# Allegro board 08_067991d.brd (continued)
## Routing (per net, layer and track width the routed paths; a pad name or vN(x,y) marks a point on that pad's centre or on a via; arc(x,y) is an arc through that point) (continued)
DGND: length 977.2
  TOP w0.203: v1(46.95,55.13) 47.15,55.33 47.15,55.51 47.2,55.56 U11.1 47.2,56.46 47.5,56.76 ; U11.38 v1(47,50.32) ; v1(41.9,51.82) U11.20 40.38,51.82 40.26,51.94 ; U11.30 v1(44.2,50.02) ; U10.9 80.51,25.65 v1(80.77,25.91) ; U11.32 v1(45.2,50.02) ; U11.44 v1(47,53.32) ; v1(42.2,50.02) U11.26 42.2,48.33 ; U11.4 v1(45.7,55.12) ; U11.10 v1(42.7,55.18)
  TOP w0.254: U12.20 50.55,82.53 C86.2 ; v1(42.04,82.3) 41.77,82.03 U12.42 ; v1(45.47,76.2) 45.24,76.42 U12.7 ; U7.C2 v1(20.83,74.41) ; U12.25 v1(48.48,85.96) ; U12.33 43.74,85.14 v1(43.31,84.71) ; U16.11 53.07,115.24 52.57,114.74 ; U12.38 39.39,84.03 C89.2 39.19,84.3 39.42,84.53 U12.37 v1(42.11,84.53) ; 46.14,44.23 46.14,46.05 45.2,46.99 U11.32 ; 43.12,44.31 43.12,46.01 44.2,47.08 U11.30 ; 52.57,114.74 v1(52.32,114.49) 52.07,114.74 U16.21 ; 52.57,114.74 U16.15 ; U9.C2 v1(20.83,97.27) ; U12.12 v1(48.34,77.6) ; U12.30 45.24,84.81 v1(45.47,84.58)
  TOP w0.305: 41.66,77.6 U12.1
  TOP w0.508: C104.1 v1(9.32,45.34) ; 43.07,112.98 R60.1 ; R60.1 43.07,114.22 ; R60.1 v1(42.29,113.6) ; 26.25,53.19 P15.8 28.61,53.19 ; 59.11,43.96 C40.1 ; C40.1 60.27,43.96 ; C40.1 v1(59.69,42.97) ; 61.26,12.7 P13.1 ; P13.1 62.69,11.26 ; P13.1 62.69,14.14 ; P13.1 64.13,12.7 ; C117.1 83.77,22.86 ; C117.1 82.87,21.81 ; C117.1 82.87,23.91 ; 40.94,28.11 C39.2 ; C39.2 v1(41.53,27.43) ; C39.2 42.11,28.11 ; P7.1 2.4,95.23 ; P7.1 2.4,91.92 ; P7.1 3.76,93.57 ; 44.65,68.73 P2.10 ; P2.10 44.65,71.09 ; P2.10 45.83,69.91 ; P2.10 43.47,69.91 ; DS12.C 51.54,2 ; DS12.C 50.9,2.65 ; DS12.C 50.25,2 ; 50.8,123.27 C73.1 ; C73.1 52.08,124.07 ; C73.1 50.8,124.87 ; C73.1 49.52,124.07 ; P15.10 28.61,50.65 ; P15.10 26.25,50.65 ; P15.10 27.43,49.47 ; 41.5,95.75 P5.4 ; P5.4 42.68,96.93 ; P5.4 42.68,94.57 ; P5.4 43.86,95.75 ; C26.2 v1(54.74,31.98) ; v1(76.2,118.49) C77.2 ; C77.2 74.99,119.55 ; C77.2 74.99,117.44 ; 8.16,81.42 C54.2 7.57,81.97 ; 50.22,78.03 C94.2 ; C94.2 51.38,78.03 ; C94.2 v1(50.8,77.27) ; 21.44,95.04 C58.2 ; C58.2 v1(21.44,96.35) ; C58.2 21.98,95.62 ; 23.86,44.83 DS2.C ; DS2.C 24.6,45.47 ; DS2.C 24.6,44.2 ; 55.36,74.42 C93.N ; C93.N 56.86,73.37 ; C93.N 58.36,74.42 ; C93.N 56.86,75.48 ; P2.6 40.75,69.91 ; P2.6 39.57,68.73 ; P2.6 39.57,71.09 ; P2.6 38.39,69.91 ; P1.1 26.78,19.22 ; P1.1 28.21,17.78 ; P1.1 25.34,17.78 ; P1.1 26.78,16.34 ; C90.2 v1(41.03,88.42) ; C90.2 40.48,87.63 ; C90.2 41.03,87.05 ; U15.7 v1(78.36,60.7) ; 52.93,25.43 C28.1 ; C28.1 53.47,24.85 ; C28.1 v1(53.47,26.67) ; P5.6 46.4,95.75 ; P5.6 45.22,96.93 ; P5.6 44.04,95.75 ; P5.6 45.22,94.57 ; C43.2 21.98,76.06 ; C43.2 v1(21.44,75.33) ; C43.2 21.44,76.65 ; 47.76,94.57 P5.8 ; P5.8 47.76,96.93 ; P5.8 46.58,95.75 ; P5.8 48.94,95.75 ; DS8.C 45.12,2 ; DS8.C 44.27,2.65 ; DS8.C 43.62,2 ; 66.9,50.45 S2.2A ; S2.2A 65.05,51.2 ; S2.2A v1(69.09,51.2) ; S2.2A 66.9,51.95 ; 28.61,55.73 P15.6 26.25,55.73 ; 71.5,61.41 U15.1 ; U15.1 72.85,61.97 ; U15.1 v1(69.85,61.97) ; U15.1 71.5,62.53 ; 55.36,87.63 C83.N ; C83.N 58.36,87.63 ; C83.N 56.86,86.58 ; C83.N 56.86,88.68 ; R62.1 60.94,115.43 ; R62.1 v1(61.85,114.81) ; R62.1 60.94,114.19 ; C75.2 v1(29.72,109.34) ; C75.2 30.92,108.28 ; C75.2 30.92,110.39 ; 37.46,72.22 P9.2 ; P9.2 38.65,73.41 ; P9.2 37.46,74.59 ; P9.2 36.28,73.41 ; 29.97,76.16 TP7.1 ; TP7.1 28.79,77.34 ; TP7.1 29.97,78.52 ; TP7.1 31.15,77.34 ; C29.2 60.99,25.43 ; C29.2 v1(60.44,26.67) ; C29.2 60.44,24.85 ; P2.14 50.91,69.91 ; P2.14 48.55,69.91 ; P2.14 49.73,71.09 ; P2.14 49.73,68.73 ; 33.56,86.58 C84.N ; C84.N 33.56,88.68 ; C84.N 35.06,87.63 ; C84.N 32.06,87.63 ; 8.16,104.28 C64.2 7.57,104.83 ; TP5.1 22.77,44.83 ; TP5.1 20.41,44.83 ; TP5.1 21.59,43.65 ; TP5.1 21.59,46.01 ; 69.59,44.83 TP6.1 ; TP6.1 71.95,44.83 ; TP6.1 70.77,46.01 ; TP6.1 70.77,43.65 ; C96.2 51.38,85.72 ; C96.2 50.22,85.72 ; C96.2 50.8,86.26 ; U14.7 v1(69.09,60.8) ; 41.67,75.56 R69.1 ; R69.1 42.24,74.94 ; R69.1 42.24,76.19 ; C110.2 v1(9.02,62.36) ; 46.01,69.91 P2.12 ; P2.12 48.37,69.91 ; P2.12 47.19,68.73 ; P2.12 47.19,71.09 ; P6.1 2.4,72.37 ; P6.1 3.76,70.71 ; P6.1 2.4,69.06 ; C11.2 v1(46.61,43.63) ; 47.63,73.91 C80.1 46.9,74.66 ; 49.12,95.75 P5.10 ; P5.10 50.3,96.93 ; P5.10 50.3,94.57 ; P5.10 51.48,95.75 ; C103.2 v1(7.29,52.58) ; C103.2 8.22,51.83 ; C103.2 8.22,53.33 ; 35.93,24.85 C20.1 ; C20.1 36.48,25.43 ; C20.1 v1(35.93,26.67) ; 61.01,58.26 U14.4 ; U14.4 63.7,58.26 ; U14.4 v1(62.36,57.52) ; 42.11,68.73 P2.8 ; P2.8 43.29,69.91 ; P2.8 42.11,71.09 ; P2.8 40.93,69.91 ; 51.09,69.91 P2.16 ; P2.16 52.27,71.09 ; P2.16 53.45,69.91 ; P2.16 52.27,68.73 ; P15.2 28.61,60.81 ; P15.2 27.43,61.99 ; P15.2 26.25,60.81 ; C56.1 v1(17.14,75.05) ; R80.2 v1(18.01,45.47) ; R80.2 17.26,46.09 ; R80.2 17.26,44.84 ; 55.62,52.88 C9.2 ; C9.2 56.16,53.47 ; C9.2 55.62,54.05 ; R18.2 R19.2 54.99,51.82 ; R18.2 54.99,50.67 ; R18.2 54.16,49.85 v1(54.23,49.78) ; C37.1 v1(57.53,48.42) ; C86.2 v1(51.44,82.78) ; 9.97,41.11 C101.2 9.07,42.16 ; 65.89,6.98 P13.GND ; P13.GND 67.13,5.73 ; P13.GND 68.38,6.98 ; P13.GND 67.13,8.23 ; P15.12 28.61,48.11 ; P15.12 26.25,48.11 ; P15.12 27.43,49.29 ; P15.12 27.43,46.93 ; 51.66,95.75 P5.12 ; P5.12 52.84,94.57 ; P5.12 52.84,96.93 ; P5.12 54.02,95.75 ; v1(82.03,28.2) C116.2 82.68,28.96 ; R58.2 v1(6.44,87.3) ; C100.1 v1(74.83,63.49) ; C79.2 53.96,122.21 ; C79.2 53.21,122.94 ; C79.2 52.46,122.21 ; P10.10 75.18,90.27 ; P10.10 74.07,89.15 ; P10.10 75.18,88.04 ; P10.10 76.3,89.15 ; C57.2 v1(21.44,98.19) ; C57.2 21.44,99.51 ; C57.2 21.98,98.92 ; U15.2 71.5,61.26 ; U15.2 71.5,60.14 ; U15.2 72.85,60.7 ; U15.2 v1(69.85,60.7) ; JP2.3 52.49,103.88 ; JP2.3 50.13,103.88 ; JP2.3 51.31,105.06 ; JP2.3 51.31,102.69 ; R106.2 v1(83.32,50.28) ; 8.57,112.4 C48.2 ; C48.2 v1(9.16,111.63) ; C48.2 9.74,112.4 ; R116.1 v1(76.71,22.35) ; P5.2 40.14,96.93 ; P5.2 40.14,94.57 ; P5.2 41.32,95.75 ; P5.2 38.96,95.75 ; R28.2 v1(58.29,58.41) ; 9.32,126.19 C47.2 ; C47.2 10.49,126.19 ; C47.2 v1(9.91,126.96) ; 77.91,48.13 D2.A ; D2.A 79.34,48.13 ; D2.A v1(78.63,47.07) ; D2.A 78.63,49 ; 9.28,55.68 C106.2 ; C106.2 8.73,56.26 ; C106.2 9.28,56.85 ; U15.4 v1(69.85,58.16) ; U15.4 71.5,58.72 ; U15.4 72.85,58.16 ; U15.4 71.5,57.6 ; v1(42.73,43.63) C13.2 43.12,44.31 ; C36.1 42.11,39.66 ; C36.1 40.94,39.66 ; C36.1 v1(41.53,38.7) ; 4.95,37.02 DS10.C ; DS10.C 5.97,37.78 ; DS10.C 5.97,36.26 ; DS10.C 6.99,37.02 ; C76.1 30.92,119.55 ; C76.1 30.92,117.44 ; C76.1 v1(29.72,118.49) ; 6.57,82 R49.2 5.95,81.42 ; 57.91,51.2 S2.1A ; S2.1A 61.95,51.2 ; S2.1A 60.1,51.95 ; S2.1A 60.1,50.45 ; R50.2 v1(6.44,64.44) ; C53.2 84.19,36.66 ; C53.2 v1(83.44,35.81) ; C53.2 82.69,36.66 ; C92.2 v1(44.44,88.42) ; 18.07,56.87 DS1.C ; DS1.C 19.77,56.87 ; DS1.C v1(18.92,55.75) ; DS1.C 18.92,57.72 ; P2.18 54.81,71.09 ; P2.18 54.81,68.73 ; P2.18 55.99,69.91 ; P2.18 53.63,69.91 ; 62.62,93.1 R77.2 ; R77.2 62.62,94.35 ; R77.2 62.05,93.73 ; P2.4 37.03,71.09 ; P2.4 37.03,68.73 ; P2.4 38.21,69.91 ; P2.4 35.85,69.91 ; C44.2 21.44,73.35 ; C44.2 21.44,72.18 ; C44.2 21.98,72.76 ; 71.5,58.87 U15.3 ; U15.3 72.85,59.43 ; U15.3 71.5,59.99 ; U15.3 v1(69.85,59.43) ; R112.1 v1(78.11,30.48) ; 28.61,58.27 P15.4 26.25,58.27 ; C16.2 68.74,64.58 ; C16.2 v1(69.72,64) ; C16.2 68.74,63.41 ; C19.2 v1(30.23,31.98) ; C38.1 v1(31.5,48.42) ; C38.1 30.91,47.43 ; C38.1 32.08,47.43 ; C21.2 v1(28.96,26.67) ; C21.2 28.96,24.85 ; C21.2 28.42,25.43 ; C91.2 v1(37.97,85.05) ; C65.2 v1(7.46,87.3) ; C69.2 v1(45.85,120.87) ; TP8.1 81.19,78.23 ; TP8.1 80.01,79.41 ; TP8.1 80.01,77.05 ; TP8.1 78.83,78.23 ; 6.57,104.86 R57.2 5.95,104.28 ; 45.52,25.42 C41.1 ; C41.1 46.69,25.42 ; C41.1 v1(46.1,24.74) ; C42.1 80.35,46.85 ; C42.1 v1(79.43,46.1) ; C42.1 80.35,45.35 ; 34.49,68.73 P2.2 ; P2.2 33.31,69.91 ; P2.2 35.67,69.91 ; P2.2 34.49,71.09 ; C72.2 v1(62.23,112.9) ; C72.2 61.42,112.15 ; C72.2 61.42,113.65 ; 2.4,115.29 P4.1 ; P4.1 v1(4.06,116.94) ; P4.1 2.4,118.59 ; C82.2 v1(87,46.99) ; R23.2 v1(64.13,64.89) ; C18.2 v1(34.66,31.98) ; 84.59,37.6 R107.1 ; R107.1 85.84,37.6 ; R107.1 v1(85.22,36.96) ; R114.1 v1(78.11,29.08) ; C27.2 v1(59.17,31.98) ; R82.2 v1(8.38,51.18) ; C55.2 v1(7.46,64.44) ; C89.2 v1(39.12,85.05) ; R25.2 v1(58.29,61.97) ; C78.1 74.99,110.39 ; C78.1 74.99,108.28 ; C78.1 v1(76.2,109.34) ; R109.1 v1(87,44.7) ; C99.2 v1(39.12,80.53) ; C102.2 v1(16.84,44.07) ; C63.1 v1(17.14,97.91) ; C98.2 v1(37.97,80.53) ; R85.1 v1(11.18,48.51)
  L2_GND w0.508: 34.49,68.73 P2.2 ; P2.2 33.31,69.91 ; P2.2 34.49,71.09 ; P2.2 35.67,69.91 ; P15.12 27.43,49.29 ; P15.12 28.61,48.11 ; P15.12 26.25,48.11 ; P15.12 27.43,46.93 ; 21.59,43.65 TP5.1 ; TP5.1 21.59,46.01 ; TP5.1 22.77,44.83 ; TP5.1 20.41,44.83 ; 26.25,53.19 P15.8 ; P15.8 27.43,54.37 ; P15.8 27.43,52.01 ; P15.8 28.61,53.19 ; 54.81,68.73 P2.18 ; P2.18 53.63,69.91 ; P2.18 54.81,71.09 ; P2.18 55.99,69.91 ; P1.1 28.21,17.78 ; P1.1 26.78,16.34 ; P1.1 25.34,17.78 ; P1.1 26.78,19.22 ; 75.18,88.04 P10.10 ; P10.10 76.3,89.15 ; P10.10 74.07,89.15 ; P10.10 75.18,90.27 ; 38.96,95.75 P5.2 ; P5.2 41.32,95.75 ; P5.2 40.14,96.93 ; P5.2 40.14,94.57 ; 26.25,50.65 P15.10 ; P15.10 28.61,50.65 ; P15.10 27.43,51.83 ; P15.10 27.43,49.47 ; P2.14 49.73,71.09 ; P2.14 48.55,69.91 ; P2.14 50.91,69.91 ; P2.14 49.73,68.73 ; P9.2 37.46,74.59 ; P9.2 38.65,73.41 ; P9.2 36.28,73.41 ; P9.2 37.46,72.22 ; 44.04,95.75 P5.6 ; P5.6 45.22,96.93 ; P5.6 45.22,94.57 ; P5.6 46.4,95.75 ; P2.12 48.37,69.91 ; P2.12 46.01,69.91 ; P2.12 47.19,68.73 ; P2.12 47.19,71.09 ; P13.GND 67.13,8.23 ; P13.GND 65.89,6.98 ; P13.GND 68.38,6.98 ; P13.GND 67.13,5.73 ; TP6.1 71.95,44.83 ; TP6.1 69.59,44.83 ; TP6.1 70.77,46.01 ; TP6.1 70.77,43.65 ; TP8.1 81.19,78.23 ; TP8.1 78.83,78.23 ; TP8.1 80.01,79.41 ; TP8.1 80.01,77.05 ; P15.4 27.43,59.45 ; P15.4 27.43,57.09 ; P15.4 28.61,58.27 ; P15.4 26.25,58.27 ; P2.10 45.83,69.91 ; P2.10 44.65,68.73 ; P2.10 44.65,71.09 ; P2.10 43.47,69.91 ; 61.26,12.7 P13.1 ; P13.1 64.13,12.7 ; P13.1 62.69,14.14 ; P13.1 62.69,11.26 ; 51.09,69.91 P2.16 ; P2.16 52.27,71.09 ; P2.16 52.27,68.73 ; P2.16 53.45,69.91 ; P2.8 43.29,69.91 ; P2.8 42.11,68.73 ; P2.8 40.93,69.91 ; P2.8 42.11,71.09 ; P2.6 40.75,69.91 ; P2.6 39.57,68.73 ; P2.6 38.39,69.91 ; P2.6 39.57,71.09 ; P15.6 28.61,55.73 ; P15.6 27.43,56.91 ; P15.6 26.25,55.73 ; P15.6 27.43,54.55 ; 41.5,95.75 P5.4 ; P5.4 42.68,96.93 ; P5.4 42.68,94.57 ; P5.4 43.86,95.75 ; 46.58,95.75 P5.8 ; P5.8 47.76,96.93 ; P5.8 48.94,95.75 ; P5.8 47.76,94.57 ; TP7.1 29.97,78.52 ; TP7.1 31.15,77.34 ; TP7.1 29.97,76.16 ; TP7.1 28.79,77.34 ; 26.25,60.81 P15.2 ; P15.2 27.43,59.63 ; P15.2 28.61,60.81 ; P15.2 27.43,61.99 ; 49.12,95.75 P5.10 ; P5.10 50.3,94.57 ; P5.10 51.48,95.75 ; P5.10 50.3,96.93 ; JP2.3 52.49,103.88 ; JP2.3 51.31,105.06 ; JP2.3 51.31,102.69 ; JP2.3 50.13,103.88 ; 35.85,69.91 P2.4 ; P2.4 37.03,71.09 ; P2.4 37.03,68.73 ; P2.4 38.21,69.91 ; P5.12 52.84,96.93 ; P5.12 52.84,94.57 ; P5.12 51.66,95.75 ; P5.12 54.02,95.75
  L3_PWR w0.508: 69.59,44.83 TP6.1 ; TP6.1 71.95,44.83 ; TP6.1 70.77,46.01 ; TP6.1 70.77,43.65 ; P13.GND 68.38,6.98 ; P13.GND 67.13,5.73 ; P13.GND 65.89,6.98 ; P13.GND 67.13,8.23 ; P5.4 43.86,95.75 ; P5.4 42.68,94.57 ; P5.4 41.5,95.75 ; P5.4 42.68,96.93 ; P15.12 28.61,48.11 ; P15.12 27.43,49.29 ; P15.12 26.25,48.11 ; P15.12 27.43,46.93 ; 54.81,68.73 P2.18 ; P2.18 54.81,71.09 ; P2.18 55.99,69.91 ; P2.18 53.63,69.91 ; P15.10 28.61,50.65 ; P15.10 27.43,51.83 ; P15.10 26.25,50.65 ; P15.10 27.43,49.47 ; 62.69,11.26 P13.1 ; P13.1 64.13,12.7 ; P13.1 62.69,14.14 ; P13.1 61.26,12.7 ; P2.4 38.21,69.91 ; P2.4 37.03,71.09 ; P2.4 37.03,68.73 ; P5.12 54.02,95.75 ; P5.12 52.84,94.57 ; P5.12 52.84,96.93 ; P1.1 28.21,17.78 ; P1.1 26.78,16.34 ; P1.1 26.78,19.22 ; P1.1 25.34,17.78 ; TP7.1 31.15,77.34 ; TP7.1 29.97,78.52 ; TP7.1 28.79,77.34 ; TP7.1 29.97,76.16 ; 49.73,68.73 P2.14 49.73,71.09 ; P5.10 50.3,96.93 ; P5.10 50.3,94.57 ; P5.10 51.48,95.75 ; P15.6 28.61,55.73 ; P15.6 26.25,55.73 ; P15.6 27.43,56.91 ; P15.6 27.43,54.55 ; P15.8 28.61,53.19 ; P15.8 26.25,53.19 ; P15.8 27.43,54.37 ; P15.8 27.43,52.01 ; 42.11,68.73 P2.8 ; P2.8 40.93,69.91 ; P2.8 42.11,71.09 ; 26.25,60.81 P15.2 ; P15.2 27.43,61.99 ; P15.2 27.43,59.63 ; P15.2 28.61,60.81 ; 47.76,96.93 P5.8 47.76,94.57 ; 45.22,94.57 P5.6 ; P5.6 45.22,96.93 ; P5.6 44.04,95.75 ; 75.18,88.04 P10.10 ; P10.10 75.18,90.27 ; P10.10 76.3,89.15 ; P10.10 74.07,89.15 ; 80.01,77.05 TP8.1 ; TP8.1 81.19,78.23 ; TP8.1 80.01,79.41 ; TP8.1 78.83,78.23 ; P15.4 28.61,58.27 ; P15.4 27.43,57.09 ; P15.4 26.25,58.27 ; P15.4 27.43,59.45 ; 34.49,68.73 P2.2 ; P2.2 33.31,69.91 ; P2.2 34.49,71.09 ; 20.41,44.83 TP5.1 ; TP5.1 21.59,46.01 ; TP5.1 22.77,44.83 ; TP5.1 21.59,43.65 ; JP2.3 52.49,103.88 ; JP2.3 51.31,102.69 ; JP2.3 51.31,105.06 ; JP2.3 50.13,103.88 ; P9.2 37.46,74.59 ; P9.2 36.28,73.41 ; P9.2 37.46,72.22 ; P9.2 38.65,73.41 ; P5.2 40.14,96.93 ; P5.2 38.96,95.75 ; P5.2 41.32,95.75 ; P5.2 40.14,94.57 ; P2.16 52.27,71.09 ; P2.16 53.45,69.91 ; P2.16 52.27,68.73
  L5_GND w0.508: P15.10 28.61,50.65 ; P15.10 27.43,49.47 ; P15.10 26.25,50.65 ; P15.10 27.43,51.83 ; P2.18 54.81,71.09 ; P2.18 55.99,69.91 ; P2.18 54.81,68.73 ; P2.18 53.63,69.91 ; P2.10 44.65,71.09 ; P2.10 45.83,69.91 ; P2.10 44.65,68.73 ; P2.10 43.47,69.91 ; 51.31,102.69 JP2.3 ; JP2.3 51.31,105.06 ; JP2.3 50.13,103.88 ; JP2.3 52.49,103.88 ; P5.10 51.48,95.75 ; P5.10 50.3,94.57 ; P5.10 49.12,95.75 ; P5.10 50.3,96.93 ; 29.97,76.16 TP7.1 ; TP7.1 31.15,77.34 ; TP7.1 28.79,77.34 ; TP7.1 29.97,78.52 ; 69.59,44.83 TP6.1 ; TP6.1 70.77,46.01 ; TP6.1 70.77,43.65 ; TP6.1 71.95,44.83 ; P2.2 35.67,69.91 ; P2.2 33.31,69.91 ; P2.2 34.49,71.09 ; P2.2 34.49,68.73 ; 52.27,68.73 P2.16 ; P2.16 51.09,69.91 ; P2.16 52.27,71.09 ; P2.16 53.45,69.91 ; P5.2 41.32,95.75 ; P5.2 40.14,94.57 ; P5.2 38.96,95.75 ; P5.2 40.14,96.93 ; 26.25,60.81 P15.2 ; P15.2 27.43,59.63 ; P15.2 27.43,61.99 ; P15.2 28.61,60.81 ; 47.19,68.73 P2.12 ; P2.12 48.37,69.91 ; P2.12 46.01,69.91 ; P2.12 47.19,71.09 ; P1.1 26.78,19.22 ; P1.1 28.21,17.78 ; P1.1 26.78,16.34 ; P1.1 25.34,17.78 ; P13.GND 67.13,8.23 ; P13.GND 67.13,5.73 ; P13.GND 68.38,6.98 ; P13.GND 65.89,6.98 ; P2.6 39.57,71.09 ; P2.6 39.57,68.73 ; P2.6 40.75,69.91 ; P2.6 38.39,69.91 ; 51.66,95.75 P5.12 ; P5.12 52.84,94.57 ; P5.12 54.02,95.75 ; P5.12 52.84,96.93 ; P15.12 28.61,48.11 ; P15.12 26.25,48.11 ; P15.12 27.43,49.29 ; P15.12 27.43,46.93 ; 46.58,95.75 P5.8 ; P5.8 47.76,94.57 ; P5.8 47.76,96.93 ; P5.8 48.94,95.75 ; 40.93,69.91 P2.8 ; P2.8 42.11,71.09 ; P2.8 43.29,69.91 ; P2.8 42.11,68.73 ; 78.83,78.23 TP8.1 ; TP8.1 80.01,79.41 ; TP8.1 80.01,77.05 ; TP8.1 81.19,78.23 ; 45.22,94.57 P5.6 ; P5.6 44.04,95.75 ; P5.6 45.22,96.93 ; P5.6 46.4,95.75 ; 62.69,11.26 P13.1 ; P13.1 64.13,12.7 ; P13.1 62.69,14.14 ; P13.1 61.26,12.7 ; 21.59,43.65 TP5.1 ; TP5.1 20.41,44.83 ; TP5.1 22.77,44.83 ; TP5.1 21.59,46.01 ; P10.10 76.3,89.15 ; P10.10 75.18,90.27 ; P10.10 74.07,89.15 ; P10.10 75.18,88.04 ; 26.25,53.19 P15.8 ; P15.8 27.43,52.01 ; P15.8 27.43,54.37 ; P15.8 28.61,53.19 ; P9.2 38.65,73.41 ; P9.2 37.46,72.22 ; P9.2 36.28,73.41 ; P9.2 37.46,74.59 ; 41.5,95.75 P5.4 ; P5.4 42.68,96.93 ; P5.4 42.68,94.57 ; P5.4 43.86,95.75 ; P15.6 27.43,56.91 ; P15.6 28.61,55.73 ; P15.6 27.43,54.55 ; P15.6 26.25,55.73 ; 49.73,68.73 P2.14 ; P2.14 49.73,71.09 ; P2.14 50.91,69.91 ; P2.14 48.55,69.91 ; 27.43,57.09 P15.4 ; P15.4 27.43,59.45 ; P15.4 26.25,58.27 ; P15.4 28.61,58.27 ; 37.03,68.73 P2.4 ; P2.4 35.85,69.91 ; P2.4 38.21,69.91 ; P2.4 37.03,71.09
  BOTTOM w0.508: P5.12 52.84,96.93 ; P5.12 54.02,95.75 ; P5.12 51.66,95.75 ; P5.12 52.84,94.57 ; 23.25,19.38 C123.1 ; C123.1 24.75,19.38 ; C123.1 24,20.1 ; TP5.1 22.77,44.83 ; TP5.1 21.59,43.65 ; TP5.1 21.59,46.01 ; TP5.1 20.41,44.83 ; 35.85,69.91 P2.4 ; P2.4 37.03,68.73 ; P2.4 37.03,71.09 ; P2.4 38.21,69.91 ; D6.3 33,33.42 ; D6.3 32.44,32.65 ; D6.3 31.89,33.42 ; D6.3 32.44,34.2 ; 26.78,16.34 P1.1 ; P1.1 25.34,17.78 ; P1.1 28.21,17.78 ; P5.6 46.4,95.75 ; P5.6 45.22,96.93 ; P5.6 45.22,94.57 ; P5.6 44.04,95.75 ; C3.2 41.65,52.07 v1(41.9,51.82) ; C3.2 41.14,52.65 ; C3.2 41.14,51.49 ; C5.2 43.51,55.62 ; C5.2 42.93,55.08 ; C5.2 42.34,55.62 ; 28.61,53.19 P15.8 26.25,53.19 ; 51.09,69.91 P2.16 ; P2.16 52.27,68.73 ; P2.16 53.45,69.91 ; P2.16 52.27,71.09 ; 44.45,55.09 C1.2 43.87,55.63 ; 26.25,60.81 P15.2 ; P15.2 27.43,59.63 ; P15.2 27.43,61.99 ; P15.2 28.61,60.81 ; 42.6,50.15 C15.2 ; C15.2 43.77,50.15 ; C15.2 43.18,50.69 ; JP2.3 51.31,105.06 ; JP2.3 51.31,102.69 ; JP2.3 52.49,103.88 ; JP2.3 50.13,103.88 ; P2.14 49.73,71.09 ; P2.14 49.73,68.73 ; P2.14 50.91,69.91 ; P2.14 48.55,69.91 ; 56.4,33.42 D4.3 ; D4.3 56.96,34.2 ; D4.3 56.96,32.65 ; D4.3 57.51,33.42 ; v1(39.12,80.53) 39.73,80.53 C87.2 C85.2 ; P2.10 44.65,71.09 ; P2.10 43.47,69.91 ; P2.10 45.83,69.91 ; P2.10 44.65,68.73 ; P9.2 37.46,74.59 ; P9.2 37.46,72.22 ; P9.2 36.28,73.41 ; P9.2 38.65,73.41 ; P5.4 42.68,96.93 ; P5.4 43.86,95.75 ; P5.4 41.5,95.75 ; P5.4 42.68,94.57 ; 52.71,53.34 C8.1 51.98,54.09 ; P13.1 64.13,12.7 ; P13.1 62.69,14.14 ; P13.1 62.69,11.26 ; P13.1 61.26,12.7 ; 67.13,5.73 P13.GND ; P13.GND 68.38,6.98 ; P13.GND 65.89,6.98 ; P13.GND 67.13,8.23 ; P2.6 40.75,69.91 ; P2.6 38.39,69.91 ; P2.6 39.57,68.73 ; P2.6 39.57,71.09 ; P5.8 47.76,96.93 ; P5.8 48.94,95.75 ; P5.8 47.76,94.57 ; P5.8 46.58,95.75 ; 28.79,77.34 TP7.1 ; TP7.1 29.97,78.52 ; TP7.1 29.97,76.16 ; TP7.1 31.15,77.34 ; C4.2 47,55.19 ; C4.2 47,54.23 v1(47,53.32) ; C4.2 46.45,54.61 ; 46.01,69.91 P2.12 ; P2.12 48.37,69.91 ; P2.12 47.19,68.73 ; P2.12 47.19,71.09 ; P5.10 50.3,96.93 ; P5.10 50.3,94.57 ; P5.10 51.48,95.75 ; P5.10 49.12,95.75 ; 34.49,68.73 P2.2 ; P2.2 34.49,71.09 ; P2.2 35.67,69.91 ; P2.2 33.31,69.91 ; P2.18 54.81,71.09 ; P2.18 55.99,69.91 ; P2.18 53.63,69.91 ; P2.18 54.81,68.73 ; v1(45.2,50.02) 45.2,49.27 C10.1 ; P2.8 43.29,69.91 ; P2.8 42.11,71.09 ; P2.8 42.11,68.73 ; P2.8 40.93,69.91 ; 53.77,109.74 C118.2 54.36,109.19 ; P10.10 76.3,89.15 ; P10.10 74.07,89.15 ; P10.10 75.18,90.27 ; P10.10 75.18,88.04 ; v1(45.7,55.12) 45.47,55.35 C2.2 ; P15.6 27.43,56.91 ; P15.6 26.25,55.73 ; P15.6 28.61,55.73 ; 51.17,55.19 C7.2 51.72,54.61 ; 70.77,43.65 TP6.1 ; TP6.1 71.95,44.83 ; TP6.1 69.59,44.83 ; TP6.1 70.77,46.01 ; v1(44.2,50.02) 44.2,50.02 C14.2 ; C88.2 v1(41.52,76.97) ; C88.2 42.07,77.72 ; C88.2 41.52,78.31 ; P15.4 28.61,58.27 ; P15.4 26.25,58.27 ; P15.4 27.43,59.45 ; TP8.1 80.01,79.41 ; TP8.1 80.01,77.05 ; TP8.1 78.83,78.23 ; TP8.1 81.19,78.23 ; 40.14,94.57 P5.2 ; P5.2 40.14,96.93 ; P5.2 41.32,95.75 ; P5.2 38.96,95.75 ; P15.12 28.61,48.11 ; P15.12 26.25,48.11 ; P15.12 27.43,46.93 ; C12.1 46.82,50.15 ; C12.1 46.23,50.69 ; C12.1 45.65,50.15 ; C81.2 37.21,51.17 v1(37.21,50.29) ; 46.45,53.59 C6.2 47,53.01 ; 28.61,50.65 P15.10 26.25,50.65
  vias: v1(2.67,114.36) v1(2.67,112.46) v1(2.67,109.92) v1(2.67,107.38) v1(2.67,100.39) v1(2.67,94.68) v1(2.67,90.87) v1(2.67,87.69) v1(2.67,85.15) v1(2.67,82.61) v1(2.67,78.8) v1(2.67,76.26) v1(2.67,68.64) v1(3.81,33.78) v1(3.81,31.24) v1(3.81,28.7) v1(3.81,26.16) v1(3.81,23.62) v1(3.81,16) v1(3.81,13.46) v1(3.81,10.92) v1(5.08,66.67) v1(5.08,64.14) v1(5.08,61.59) v1(5.08,59.05) v1(5.08,56.52) v1(5.08,53.98) v1(5.08,51.43) v1(5.08,48.89) v1(5.08,46.35) v1(5.08,43.81) v1(5.08,41.27) v1(5.08,38.73) v1(5.08,36.2) v1(5.21,114.36) v1(5.21,112.46) v1(5.21,109.92) v1(5.21,107.38) v1(5.21,94.68) v1(5.21,90.87) v1(5.21,87.69) v1(5.21,85.15) v1(5.21,82.61) v1(5.21,71.18) v1(5.21,68.64) v1(6.22,78.74) v1(6.22,76.2) v1(6.22,61.34) v1(6.22,60.71) v1(6.22,60.07) v1(6.22,58.93) v1(6.22,58.29) v1(6.22,57.66) v1(6.22,56.39) v1(6.22,55.75) v1(6.22,55.12) v1(6.86,61.34) v1(6.86,60.71) v1(6.86,60.07) v1(6.86,58.93) v1(6.86,58.29) v1(6.86,57.66) v1(6.86,56.39) v1(6.86,55.75) v1(6.86,55.12) v1(7.62,51.43) v1(7.62,48.89) v1(7.62,46.35) v1(7.62,43.81) v1(7.62,33.66) v1(7.62,10.79) v1(8,42.8) v1(8,42.16) v1(8,41.53) v1(8.76,109.86) v1(8.76,107.31) v1(8.76,100.33) v1(8.76,94.61) v1(8.76,90.8) v1(8.76,87.63) v1(8.76,85.09) v1(8.76,82.55) v1(8.76,78.74) v1(8.76,76.2) v1(8.76,68.58) v1(8.76,64.14) v1(10.16,135.26) v1(10.16,132.72) v1(10.16,10.79) v1(11.18,31.88) v1(11.18,31.12) v1(11.3,109.86) v1(11.3,107.31) v1(11.3,100.33) v1(11.3,90.8) v1(11.3,87.63) v1(11.3,85.09) v1(11.3,82.55) v1(11.3,78.74) v1(11.3,76.2) v1(11.3,68.58) v1(11.3,64.14) v1(11.94,31.88) v1(11.94,31.12) v1(12.7,135.26) v1(12.7,132.72) v1(12.7,10.79) v1(13.21,49.67) v1(13.21,48.65) v1(13.72,49.16) v1(13.84,125.09) v1(13.84,122.55) v1(13.84,120.02) v1(13.84,117.47) v1(13.84,107.31) v1(13.84,100.33) v1(13.84,97.79) v1(13.84,94.61) v1(13.84,90.8) v1(13.84,87.63) v1(13.84,85.09) v1(13.84,82.55) v1(13.84,78.74) v1(13.84,76.2) v1(13.84,73.66) v1(13.84,71.12) v1(13.84,68.58) v1(13.84,64.14) v1(14.22,49.67) v1(14.22,48.65) v1(15.24,135.26) v1(15.24,132.72) v1(15.24,10.79) v1(15.24,8.25) v1(15.24,5.71) v1(15.24,3.17) v1(16.38,125.09) v1(16.38,122.55) v1(16.38,120.02) v1(16.38,117.47) v1(16.38,107.31) v1(16.38,100.33) v1(16.38,97.79) v1(16.38,94.61) v1(16.38,90.8) v1(16.38,87.63) v1(16.38,85.09) v1(16.38,82.55) v1(16.38,78.74) v1(16.38,76.2) v1(16.38,73.66) v1(16.38,71.12) v1(16.38,68.58) v1(16.38,64.14) v1(17.78,135.26) v1(17.78,132.72) v1(17.78,53.98) v1(17.78,51.43) v1(17.78,48.89) v1(17.78,46.35) v1(17.78,38.73) v1(17.78,36.2) v1(17.78,33.66) v1(17.78,31.12) v1(17.78,28.58) v1(17.78,18.41) v1(17.78,15.88) v1(17.78,13.34) v1(17.78,10.79) v1(17.78,8.25) v1(17.78,5.71) v1(17.78,3.17) v1(18.92,125.09) v1(18.92,122.55) v1(18.92,120.02) v1(18.92,117.47) v1(18.92,107.31) v1(18.92,87.63) v1(18.92,85.09) v1(18.92,82.55) v1(19.05,64.14) v1(20.32,135.26) v1(20.32,132.72) v1(20.32,59.05) v1(20.32,56.52) v1(20.32,53.98) v1(20.32,51.43) v1(20.32,48.89) v1(20.32,46.35) v1(20.32,38.73) v1(20.32,36.2) v1(20.32,33.66) v1(20.32,18.41) v1(20.32,15.88) v1(20.32,13.34) v1(20.32,10.79) v1(20.32,8.25) v1(20.32,5.71) v1(20.32,3.17) v1(20.63,37.81) v1(20.63,37.3) v1(20.63,36.79) v1(20.95,69.22) v1(20.95,67.31) v1(21.14,37.81) v1(21.14,37.3) v1(21.14,36.79) v1(21.4,125.03) v1(21.46,122.55) v1(21.46,120.02) v1(21.46,117.47) v1(21.46,107.31) v1(21.46,102.23) v1(21.46,82.55) v1(21.59,63.37) v1(21.59,60.77) v1(21.59,58.17) v1(21.59,55.56) v1(21.59,52.9) v1(21.59,50.29) v1(21.65,37.81) v1(21.65,37.3) v1(21.65,36.79) v1(22.86,135.26) v1(22.86,132.72) v1(22.86,84.45) v1(22.86,46.35) v1(22.86,43.81) v1(22.86,33.66) v1(22.86,20.95) v1(22.86,18.41) v1(22.86,15.88) v1(22.86,13.34) v1(22.86,10.79) v1(22.86,8.25) v1(22.86,5.71) v1(22.86,3.17) v1(23.18,50.86) v1(23.24,48.77) v1(23.49,76.83) v1(23.49,74.3) v1(23.49,72.39) v1(23.49,69.22) v1(23.49,67.31) v1(24,109.86) v1(24,107.31) v1(24,102.23) v1(24,99.69) v1(24,97.16) v1(24,94.61) v1(24,92.08) v1(24,89.53) v1(25.4,84.45) v1(25.4,79.38) v1(25.4,76.83) v1(25.4,74.3) v1(25.4,69.22) v1(25.4,67.31) v1(25.4,41.27) v1(25.4,36.2) v1(25.4,33.66) v1(25.4,10.79) v1(25.4,5.71) v1(25.4,3.17) v1(25.53,87) v1(25.65,82.68) v1(25.65,72.26) v1(26.03,45.85) v1(26.8,63.5) v1(27.3,69.22) v1(27.3,67.31) v1(27.69,71.37) v1(27.94,135.26) v1(27.94,132.72) v1(27.94,122.55) v1(27.94,120.02) v1(27.94,114.94) v1(27.94,112.39) v1(27.94,109.86) v1(27.94,89.53) v1(27.94,87) v1(27.94,81.41) v1(27.94,79.38) v1(27.94,76.83) v1(27.94,74.3) v1(27.94,41.27) v1(27.94,38.73) v1(27.94,36.2) v1(27.94,33.66) v1(27.94,31.12) v1(27.94,28.58) v1(27.94,5.71) v1(27.94,3.17) v1(28.32,85.72) v1(28.32,83.95) v1(28.38,45.85) v1(28.58,69.22) v1(28.58,67.31) v1(28.58,48.96) v1(29.02,58.86) v1(28.96,57.4) v1(28.96,53.21) v1(29.02,51.31) v1(29.46,73.02) v1(29.72,75.56) v1(29.65,54.74) v1(30.35,82.68) v1(30.35,38.73) v1(30.35,36.2) v1(30.35,33.66) v1(30.35,31.12) v1(30.35,28.58) v1(30.48,135.26) v1(30.48,114.94) v1(30.48,112.39) v1(30.48,92.08) v1(30.48,89.53) v1(30.48,87) v1(30.48,79.38) v1(30.48,71.12) v1(30.48,8.25) v1(30.48,5.71) v1(30.48,3.17) v1(30.61,57.72) v1(30.8,55.63) v1(30.8,54.29) v1(30.73,41.27) v1(30.86,53.15) v1(31.18,49.34) v1(31.24,74.8) v1(31.31,64.71) v1(31.34,88.13) v1(31.34,87.62) v1(31.34,87.11) v1(31.43,59.25) v1(31.69,42.65) v1(31.75,56.64) v1(31.75,55.44) v1(31.75,54.29) v1(31.85,88.13) v1(31.85,87.62) v1(31.85,87.11) v1(31.94,49.34) v1(32.13,70.48) v1(32.38,73.02) v1(32.38,69.22) v1(32.38,66.04) v1(32.38,63.5) v1(32.45,56.9) v1(32.77,85.72) v1(32.77,83.95) v1(33.02,135.26) v1(33.02,114.94) v1(33.02,112.39) v1(33.02,92.08) v1(33.02,89.53) v1(33.02,79.38) v1(33.02,76.58) v1(33.02,8.25) v1(33.02,5.71) v1(33.15,81.41) v1(33.4,71.75) v1(34.04,43.94) v1(34.29,74.93) v1(34.54,82.68) v1(34.54,40.64) v1(34.54,38.73) v1(34.54,36.2) v1(34.54,33.66) v1(34.54,31.12) v1(34.54,28.58) v1(34.67,78.23) v1(34.67,73.02) v1(35.18,71.37) v1(35.18,65.91) v1(35.29,46.53) v1(35.56,135.26) v1(35.56,114.94) v1(35.56,112.39) v1(35.56,92.08) v1(35.56,89.53) v1(35.56,13.34) v1(35.56,10.79) v1(35.56,8.25) v1(35.56,5.71) v1(35.81,74.17) v1(35.81,63.75) v1(36.2,76.83) v1(36.13,43.95) v1(36.32,72.26) v1(36.45,79.25) v1(36.45,66.04) v1(36.53,41.27) v1(36.83,46.99) v1(37.46,74.96) v1(37.59,77.85) v1(37.97,64.14) v1(38.1,135.26) v1(38.1,132.72) v1(38.1,114.94) v1(38.1,112.39) v1(38.1,107.31) v1(38.1,104.77) v1(38.1,94.61) v1(38.1,92.08) v1(38.1,89.53) v1(38.03,44.06) v1(38.1,33.66) v1(38.1,31.12) v1(38.1,28.58) v1(38.1,18.41) v1(38.1,15.88) v1(38.1,13.34) v1(38.1,10.79) v1(38.1,8.25) v1(38.1,5.71) v1(38.1,3.17) v1(38.43,41.37) v1(38.48,72.26) v1(38.48,70.99) v1(39.12,75.31) v1(39.12,45.09) v1(39.18,51.69) v1(39.62,115.7) v1(39.62,114.43) v1(39.62,113.03) v1(39.62,78.11) v1(40.11,42.27) v1(40.39,75.31) v1(40.64,135.26) v1(40.64,132.72) v1(40.64,130.18) v1(40.64,127.64) v1(40.64,125.09) v1(40.64,122.55) v1(40.64,107.31) v1(40.64,104.77) v1(40.64,102.23) v1(40.64,99.69) v1(40.64,97.16) v1(40.64,33.66) v1(40.64,31.12) v1(40.64,23.49) v1(40.64,20.95) v1(40.64,18.41) v1(40.64,15.88) v1(40.64,13.34) v1(40.64,10.79) v1(40.64,8.25) v1(40.64,5.71) v1(40.64,3.17) v1(40.89,70.99) v1(41.27,97.92) v1(41.47,75.56) v1(41.46,43.62) v1(42.11,48.06) v1(42.67,79.69) v1(42.8,44.97) v1(42.93,54.09) v1(42.93,53.33) v1(42.93,52.57) v1(42.93,51.81) v1(42.93,51.04) v1(43.18,135.26) v1(43.18,132.72) v1(43.18,130.18) v1(43.18,127.64) v1(43.18,125.09) v1(43.18,122.55) v1(43.18,104.77) v1(43.18,102.23) v1(43.18,99.69) v1(43.18,97.16) v1(43.18,33.66) v1(43.18,23.49) v1(43.18,20.95) v1(43.18,18.41) v1(43.18,15.88) v1(43.18,13.34) v1(43.18,10.79) v1(43.18,8.25) v1(43.18,5.71) v1(43.18,3.17) v1(43.43,100.97) v1(43.69,54.09) v1(43.69,53.33) v1(43.69,52.57) v1(43.69,51.81) v1(43.69,51.04) v1(43.81,97.92) v1(44.45,106.17) v1(44.45,99.82) v1(44.45,54.09) v1(44.45,53.33) v1(44.45,52.57) v1(44.45,51.81) v1(44.45,51.04) v1(44.7,102.23) v1(44.83,104.52) v1(44.83,82.93) v1(45.09,101.09) v1(45.09,99.19) v1(45.21,54.09) v1(45.21,53.33) v1(45.21,52.57) v1(45.21,51.81) v1(45.21,51.04) v1(45.29,40.76) v1(45.47,81.15) v1(45.72,135.26) v1(45.72,132.72) v1(45.72,130.18) v1(45.72,127.64) v1(45.72,125.09) v1(45.72,122.55) v1(45.72,107.31) v1(45.72,100.46) v1(45.72,98.42) v1(45.72,97.16) v1(45.72,31.75) v1(45.72,23.49) v1(45.72,20.95) v1(45.72,18.41) v1(45.72,15.88) v1(45.72,13.34) v1(45.72,10.79) v1(45.72,8.25) v1(45.72,5.71) v1(45.72,3.17) v1(45.97,91.31) v1(45.97,84.58) v1(45.97,83.69) v1(45.97,54.09) v1(45.97,53.33) v1(45.97,52.57) v1(45.97,51.81) v1(45.97,51.04) v1(46.23,106.05) v1(46.86,108.46) v1(46.99,41.91) v1(47.24,97.16) v1(47.24,84.58) v1(47.24,83.31) v1(47.24,81.41) v1(47.5,91.82) v1(47.62,36.83) v1(47.62,33.66) v1(47.62,31.75) v1(47.75,97.92) v1(47.94,43.62) v1(48.26,135.26) v1(48.26,132.72) v1(48.26,130.18) v1(48.26,127.64) v1(48.26,125.09) v1(48.26,122.55) v1(48.26,97.16) v1(48.26,75.56) v1(48.26,74.17) v1(48.26,23.49) v1(48.26,20.95) v1(48.26,18.41) v1(48.26,15.88) v1(48.26,13.34) v1(48.26,10.79) v1(48.26,8.25) v1(48.26,5.71) v1(48.26,3.17) v1(48.39,88.27) v1(48.39,87.38) v1(48.64,72.26) v1(48.89,39.37) v1(49.15,107.7) v1(49.29,42.27) v1(49.66,89.92) v1(49.66,75.31) v1(49.66,73.79) v1(49.78,97.92) v1(49.91,108.97) v1(49.91,100.46) v1(50.01,85.72) v1(50.04,86.87) v1(50.16,71.5) v1(50.16,45.21) v1(50.16,29.84) v1(50.16,27.94) v1(50.55,101.22) v1(50.8,135.26) v1(50.8,132.72) v1(50.8,130.18) v1(50.8,127.64) v1(50.8,125.09) v1(50.8,98.42) v1(50.8,97.16) v1(50.8,72.77) v1(50.8,38.73) v1(50.8,36.83) v1(50.8,18.41) v1(50.8,15.88) v1(50.8,13.34) v1(50.8,10.79) v1(50.8,8.25) v1(50.8,5.71) v1(50.8,3.17) v1(50.97,41.37) v1(51.18,62.55) v1(51.37,44.06) v1(51.43,102.23) v1(51.43,71.5) v1(51.56,115.25) v1(51.56,114.49) v1(51.56,113.73) v1(52.07,100.58) v1(52.2,56.01) v1(52.32,115.25) v1(52.32,113.73) v1(52.32,97.92) v1(52.45,77.09) v1(52.58,106.93) v1(52.58,105.54) v1(52.7,33.66) v1(52.7,29.84) v1(52.7,27.94) v1(52.87,41.27) v1(52.96,101.47) v1(52.96,76.45) v1(52.96,72.77) v1(52.96,71.5) v1(52.96,56.01) v1(53.09,115.25) v1(53.09,114.49) v1(53.09,113.73) v1(53.21,123.19) v1(53.27,43.95) v1(53.34,135.26) v1(53.34,132.72) v1(53.34,130.18) v1(53.34,127.64) v1(53.34,125.09) v1(53.34,89.53) v1(53.34,59.05) v1(53.34,57.78) v1(53.34,5.71) v1(53.34,3.17) v1(53.59,62.23) v1(53.59,61.34) v1(53.72,78.36) v1(53.72,77.6) v1(53.66,64.2) v1(53.85,105.92) v1(53.98,107.06) v1(54.23,76.45) v1(54.23,72.77) v1(54.23,71.5) v1(54.61,101.6) v1(54.86,97.92) v1(54.86,40.64) v1(54.86,38.73) v1(54.86,36.2) v1(54.86,33.66) v1(54.86,31.12) v1(54.86,28.58) v1(55.12,49.78) v1(55.12,43.94) v1(55.24,96.52) v1(55.24,93.98) v1(55.24,92.08) v1(55.37,101.6) v1(55.37,89.53) v1(55.37,85.98) v1(55.88,135.26) v1(55.88,132.72) v1(55.88,130.18) v1(55.88,127.64) v1(55.88,125.09) v1(55.88,122.55) v1(55.88,71.5) v1(55.88,59.05) v1(55.88,57.78) v1(55.88,5.71) v1(55.88,3.17) v1(56.08,85.98) v1(56.58,54.17) v1(56.64,105.28) v1(56.64,102.49) v1(56.64,100.46) v1(56.64,96.52) v1(56.64,93.98) v1(56.64,91.95) v1(56.64,89.53) v1(56.64,83.57) v1(56.64,82.3) v1(57.28,66.74) v1(57.4,97.92) v1(57.71,42.65) v1(58.42,135.26) v1(58.42,132.72) v1(58.42,130.18) v1(58.42,127.64) v1(58.42,125.09) v1(58.42,107.31) v1(58.42,94.61) v1(58.42,92.08) v1(58.42,89.53) v1(58.42,79.38) v1(58.42,71.75) v1(58.42,68.33) v1(58.42,10.79) v1(58.42,8.25) v1(58.42,5.71) v1(58.42,3.17) v1(58.57,88.15) v1(58.57,87.64) v1(58.57,87.13) v1(58.57,74.93) v1(58.57,74.43) v1(58.57,73.93) v1(58.67,41.27) v1(59.08,88.15) v1(59.08,87.64) v1(59.08,87.13) v1(59.08,74.94) v1(59.08,74.43) v1(59.08,73.93) v1(59.05,38.73) v1(59.05,36.2) v1(59.05,33.66) v1(59.05,31.12) v1(59.05,28.58) v1(59.94,97.92) v1(60.96,135.26) v1(60.96,132.72) v1(60.96,130.18) v1(60.96,127.64) v1(60.96,125.09) v1(60.96,122.55) v1(60.96,107.31) v1(60.96,102.23) v1(60.96,95.89) v1(60.96,93.34) v1(60.96,81.91) v1(60.96,71.75) v1(60.96,56.52) v1(60.96,41.27) v1(60.96,38.73) v1(60.96,36.2) v1(60.96,33.66) v1(60.96,31.12) v1(60.96,10.79) v1(60.96,8.25) v1(60.96,5.71) v1(62.36,121.28) v1(62.61,72.96) v1(63.5,135.26) v1(63.5,132.72) v1(63.5,130.18) v1(63.5,127.64) v1(63.5,125.09) v1(63.5,107.31) v1(63.5,104.77) v1(63.5,102.23) v1(63.5,99.69) v1(63.5,95.89) v1(63.5,81.91) v1(63.5,79.38) v1(63.5,76.2) v1(63.5,43.81) v1(63.5,41.27) v1(63.5,38.73) v1(63.5,36.2) v1(63.5,18.41) v1(63.5,15.88) v1(63.5,10.79) v1(63.5,8.25) v1(63.5,5.71) v1(64.26,122.43) v1(64.77,64.14) v1(66.01,121.51) v1(66.01,115.57) v1(66.01,114.17) v1(66.01,112.9) v1(66.01,111.51) v1(66.04,135.26) v1(66.04,132.72) v1(66.04,130.18) v1(66.04,127.64) v1(66.04,125.09) v1(66.04,120.27) v1(66.04,116.71) v1(66.04,107.31) v1(66.04,104.77) v1(66.04,102.23) v1(66.04,99.69) v1(66.04,95.89) v1(66.04,41.27) v1(66.04,38.73) v1(66.04,18.41) v1(66.04,15.88) v1(66.04,13.34) v1(66.04,10.79) v1(66.04,3.17) v1(66.55,84.45) v1(68.58,135.26) v1(68.58,132.72) v1(68.58,114.94) v1(68.58,112.39) v1(68.58,92.08) v1(68.58,84.45) v1(68.58,79.38) v1(68.58,76.2) v1(68.58,18.41) v1(68.58,15.88) v1(68.58,13.34) v1(68.58,10.79) v1(68.58,3.17) v1(70.46,38.32) v1(70.46,37.82) v1(70.46,37.31) v1(70.97,38.32) v1(70.97,37.82) v1(70.97,37.31) v1(71.12,135.26) v1(71.12,114.94) v1(71.12,112.39) v1(71.12,92.08) v1(71.12,84.45) v1(71.12,81.91) v1(71.12,79.38) v1(71.12,76.2) v1(71.12,66.67) v1(71.12,48.89) v1(71.12,18.41) v1(71.12,15.88) v1(71.12,13.34) v1(71.12,10.79) v1(71.12,8.25) v1(71.12,5.71) v1(71.12,3.17) v1(71.48,38.32) v1(71.48,37.82) v1(71.48,37.31) v1(71.88,50.93) v1(72.01,53.66) v1(73.66,135.26) v1(73.66,114.94) v1(73.66,112.39) v1(73.66,92.08) v1(73.66,61.59) v1(73.66,56.52) v1(73.66,53.98) v1(73.66,51.43) v1(73.66,48.89) v1(73.66,46.35) v1(73.66,38.73) v1(73.66,36.2) v1(73.66,10.79) v1(73.66,8.25) v1(73.66,5.71) v1(73.66,3.17) v1(74.3,84.45) v1(74.3,79.38) v1(76.2,135.26) v1(76.2,120.02) v1(76.2,114.94) v1(76.2,112.39) v1(76.2,107.31) v1(76.2,94.61) v1(76.2,92.08) v1(76.2,81.91) v1(76.2,10.79) v1(76.2,8.25) v1(76.2,5.71) v1(76.2,3.17) v1(78.74,135.26) v1(78.74,132.72) v1(78.74,122.55) v1(78.74,120.02) v1(78.74,117.47) v1(78.74,114.94) v1(78.74,112.39) v1(78.74,109.86) v1(78.74,107.31) v1(78.74,104.77) v1(78.74,97.16) v1(78.74,94.61) v1(78.74,92.08) v1(78.74,89.53) v1(78.74,87) v1(78.74,81.91) v1(78.74,79.38) v1(78.74,76.83) v1(78.74,74.3) v1(78.74,71.75) v1(78.74,69.22) v1(78.74,66.67) v1(78.74,48.89) v1(79.25,26.67) v1(79.25,25.91) v1(80.01,26.67) v1(80.01,25.91) v1(80.77,26.67) v1(81.28,130.18) v1(81.28,127.64) v1(81.28,125.09) v1(81.28,122.55) v1(81.28,120.02) v1(81.28,117.47) v1(81.28,114.94) v1(81.28,112.39) v1(81.28,109.86) v1(81.28,107.31) v1(81.28,104.77) v1(81.28,102.23) v1(81.28,99.69) v1(81.28,97.16) v1(81.28,94.61) v1(81.28,92.08) v1(81.28,89.53) v1(81.28,87) v1(81.28,84.45) v1(81.28,81.91) v1(81.28,79.38) v1(81.28,76.83) v1(81.28,53.98) v1(81.28,51.43) v1(82.04,27.56) v1(82.17,42.8) v1(82.17,41.78) v1(82.55,73.66) v1(82.55,68.58) v1(82.55,63.5) v1(82.55,59.05) v1(82.55,24.77) v1(82.55,24.13) v1(82.68,28.19) v1(82.68,27.56) v1(82.8,42.29) v1(83.31,24.77) v1(83.31,24.13) v1(83.44,42.8) v1(83.44,41.78) v1(84.33,34.29) v1(84.33,31.75) v1(84.33,29.21) v1(84.33,26.67) v1(84.33,24.13) v1(84.33,21.59) v1(84.33,19.05) v1(84.33,16.51) v1(84.33,13.97)
VDD_3V3: length 39.6
  TOP w0.254: v1(17.14,96.91) C63.2 18.27,97.27 U9.A2 ; C92.1 43.24,87.43 U12.34 ; U12.48 40.67,79.03 40.51,78.87 v1(40.51,78.49) ; v1(17.14,74.05) C56.2 18.27,74.41 U7.A2 ; U12.39 41.88,83.53 v1(42.18,83.82) ; C90.1 42.24,87.42 U12.36
  TOP w0.508: R63.1 v1(50.8,106.16) ; R64.1 v1(52.96,99.31) ; C92.1 v1(43.44,88.38) ; R73.2 v1(43.12,72.41) ; R95.1 v1(54.99,99.31) ; C97.2 v1(40.39,89.41) ; E11.1 v1(73.91,64.76) ; R83.1 v1(9.8,43.94) ; R72.2 v1(53.28,82.03) ; TP9.1 18.09,61.47 18.1,61.46 R16.1 ; TP9.1 15.11,60.29 ; TP9.1 13.93,61.47 ; C90.1 v1(42.03,88.38) ; R65.1 v1(56.39,106.16) ; R71.2 v1(39,90.8) ; E1.2 v1(34.49,62.22) ; E5.2 v1(58.93,49.02)
  L4_PWR w0.508: JP2.1 46.23,105.06 ; JP2.1 47.41,103.88 ; JP2.1 46.23,102.69 ; 15.11,60.29 TP9.1 ; TP9.1 16.29,61.47 ; TP9.1 13.93,61.47 ; TP9.1 15.11,62.65
  BOTTOM w0.508: C88.1 40.52,77.85 40.51,77.86 v1(40.51,78.49) ; R99.1 v1(55.5,107.19)
  vias: v1(11.81,62.1) v1(11.81,61.47) v1(11.81,60.83) v1(11.81,60.32) v1(12.45,62.1) v1(12.45,61.47) v1(13.08,62.1) v1(13.08,61.47) v1(38.73,88.15) v1(38.73,87.64) v1(38.73,87.13) v1(39.24,88.15) v1(39.24,87.64) v1(39.24,87.13) v1(55.8,78.87) v1(56.31,78.87) v1(66.29,21.08) v1(66.29,20.57) v1(66.29,20.07) v1(66.8,20.07) v1(67.31,20.07) v1(67.82,21.08) v1(67.82,20.57) v1(67.82,20.07)
VDD_5V: length 92.7
  TOP w0.254: U10.1 81.01,28.93 C116.1
  TOP w0.508: R108.1 v1(87,45.85) ; R110.1 v1(84.19,47.11) ; R111.2 v1(75.56,30.48) ; R113.2 v1(75.56,29.08)
  L3_PWR w1.016: v1(81.03,30.61) v1(81.66,30.61) v1(81.66,29.97) v1(81.03,29.97) v1(81.03,30.61) ; v1(81.03,30.61) 81.03,32.51 80.14,33.4 v1(77.72,33.4) ; v1(77.09,34.04) 77.09,56.01 75.08,58.01 71.86,58.01 69.09,55.24 55.5,55.24 ; v1(77.09,34.04) v1(77.72,34.04) v1(77.72,33.4) ; v1(77.09,34.04) v1(77.09,33.4) v1(77.72,33.4) ; 55.5,55.24 v1(54.99,54.74) v1(54.99,55.24) 55.5,55.24
  BOTTOM w0.254: v1(81.03,30.61) 80.39,31.24 76.32,31.24 v1(75.56,30.48) v1(75.56,29.08) ; v1(77.72,34.04) 81.53,34.04 82.55,35.05 85.72,35.05 86.23,35.56 86.23,45.09 v1(87,45.85) 85.73,47.11 v1(84.19,47.11)
VIN0: length 55.1
  TOP w0.178: U12.4 v1(43.74,78.87)
  TOP w0.203: R46.2 v1(23.44,115.76)
  BOTTOM w0.178: v1(43.74,78.87) 44.32,79.45 44.32,81.91 43.01,83.22 37.93,83.22 34.8,86.36 27.3,86.36 24.89,88.77 24.89,114.31 v1(23.44,115.76)
VIN1: length 67.1
  TOP w0.178: U12.2 v1(42.74,78.87)
  TOP w0.203: R45.2 v1(23.44,125.54)
  BOTTOM w0.178: v1(42.74,78.87) 42.81,78.87 43.94,80 43.94,81.76 42.86,82.84 37.68,82.84 35.94,84.58 26.29,84.58 22.54,88.33 22.54,117.09 23.44,118 v1(23.44,125.54)
AD243X_ADR2/IO2/MCLK: length 107.7
  TOP w0.178: v1(31.75,51.24) R11.1 ; v1(50.8,111.76) 51.07,112.03 U16.1
  TOP w0.254: U12.32 44.24,85.03 44.58,84.69 v1(44.58,84.68)
  L3_PWR w0.178: v1(44.58,84.68) 43.53,85.72 37.15,85.72 35.43,84.01 35.43,77.34 27.88,69.79 24.84,69.79 20.95,65.9 20.95,49.91 22.76,48.11 P15.11
  BOTTOM w0.178: v1(31.75,51.24) 30.04,51.24 28.32,49.53 26.31,49.53 P15.11 ; v1(50.8,111.76) 50.29,111.25 50.29,111 42.29,103 42.29,99.85 36.83,94.39 36.83,86.49 37.34,85.98 43.28,85.98 v1(44.58,84.68)
AD243X_BCLK: length 75.7
  TOP w0.178: v1(45.25,79.88) 45.85,79.88 46.29,79.44 46.29,78.17 46.24,78.12 U12.9 ; R68.1 52.07,109.72 v1(52.07,108.33) ; R1.2 v1(37.03,63.43) 37.03,62.85 38.29,61.59 40.61,61.59 40.61,61.59 R10.1 ; v1(46.61,82.04) 46.62,82.03 U12.19
  L3_PWR w0.178: v1(37.03,63.43) 35.81,64.65 35.81,71.12 36.33,71.64 43.32,71.64 46.61,74.93 46.61,75.95 44.83,77.72 44.83,79.46 v1(45.25,79.88) 46.61,81.24 v1(46.61,82.04) 46.61,98.68 43.94,101.35 43.94,104.65 47.62,108.33 v1(52.07,108.33)
AD243X_GPIO7: length 73.1
  TOP w0.178: R14.2 37.34,56.95 37.34,56.51 39.03,54.82 v1(40.13,54.82) U11.14
  L3_PWR w0.178: v1(40.13,54.82) 41.48,54.82 42.55,55.88 49.25,55.88 54.75,50.38 65.06,50.38 67.82,47.62 TP4.1 71.89,47.62 72.77,46.74 72.77,29.34 75.44,26.67 75.44,22.07 75.79,21.72
  L3_PWR w0.203: 75.79,21.72 76.17,21.34 v1(77.6,21.34)
  BOTTOM w0.203: R117.2 v1(77.6,21.34)
AD243X_IOVDD: length 53.7
  TOP w0.178: v1(40.1,51.42) 40.14,51.42 40.24,51.32 U11.21 ; v1(42.2,56.63) U11.11
  TOP w0.254: C86.1 50.55,81.53 U12.18
  TOP w0.508: R78.1 v1(34.86,56.52) ; R21.1 v1(68.83,48.39) ; C86.1 v1(51.44,81.78) ; R86.1 v1(34.86,55.37) ; R98.2 v1(47.38,72.52) ; R26.1 v1(57.53,53.18) ; R17.1 v1(32.89,49.91)
  L4_PWR w0.508: TP3.1 33.19,61.59 ; TP3.1 32,60.41 ; TP3.1 32,62.78 ; TP3.1 30.82,61.59
  BOTTOM w0.508: C3.1 40.1,52.03 v1(40.1,51.42) ; v1(68.83,48.39) 64.04,53.18 v1(57.53,53.18) 57.29,53.42 57.29,55.11 54.74,57.66 54.74,58.8 52.58,60.96 47.5,60.96 45.47,58.94 R104.2 43.69,57.39 C5.1 42.33,56.62 42.33,56.63 v1(42.2,56.63) ; R97.1 33.4,51.18 32.89,50.67 v1(32.89,49.91)
  vias: v1(51.18,88.13) v1(51.18,87.62) v1(51.18,87.11) v1(51.69,88.13) v1(51.69,87.62) v1(51.69,87.11)
AD243X_IRQ: length 48.2
  TOP w0.178: R8.2 v1(54.81,63.43) ; R20.1 29.21,45.35 29.21,49.15 30.63,50.57 34.52,50.57 34.73,50.37 R17.2 v1(36.35,49.91) 36.44,49.82 U11.24
  L3_PWR w0.178: v1(36.35,49.91) 36.35,50.72 35.43,51.63 35.43,57.75 38.22,60.54 45.68,60.54 46.1,60.96 50.8,60.96 53.27,63.43 v1(54.81,63.43)
AD243X_MISO: length 10.4
  TOP w0.178: R100.2 31.37,56.01 29.97,57.4 29.97,58.8 29.34,59.44 26.26,59.44 P15.1
AD243X_MOSI: length 9
  TOP w0.178: P15.3 26.14,57.02 28.45,57.02 30.61,54.86 R101.2
AD243X_PDM_CLK: length 83.9
  TOP w0.178: R7.2 v1(51.43,64.21) ; R14.1 v1(34.8,57.66)
  L3_PWR w0.178: v1(33.61,46.53) 33.27,46.87 33.27,48.51 34.16,49.4 34.16,57.02 v1(34.8,57.66) 38.06,60.92 42,60.92 43.82,62.74 44.45,62.74 45.47,61.72 48.95,61.72 v1(51.43,64.21)
  BOTTOM w0.178: 48.17,41.15 49.53,41.15 52.58,44.2 52.58,45.45 53.61,46.48 v1(53.61,46.53) ; 48.17,41.15 47.37,41.15 44.07,37.85 43.61,37.85 43.31,38.15 43.31,38.74 44.2,39.62 44.2,40.17 v1(43.61,40.76) 43.16,41.21 39.95,41.21 38.08,43.07 33.13,43.07 32.13,44.07 32.13,44.83 32.38,45.09 34.16,45.09 34.42,45.34 34.42,45.73 v1(33.61,46.53) ; 48.17,41.15 48.17,35.98 42.8,30.61 42.8,30.02 v1(43.61,29.21)
AD243X_SCK: length 8.5
  TOP w0.178: P15.5 26.26,54.36 28.96,54.36 29.6,53.71 R102.2
AD243X_SCL: length 61.7
  TOP w0.178: R86.2 37.9,54.1 v1(37.97,54.1) 38.26,53.82 U11.16 ; S1.2A 71.26,53.86 v1(71.88,54.48) 71.24,55.13 S1.1A
  BOTTOM w0.178: v1(71.88,54.48) 71.12,53.72 68.99,53.72 57.05,65.66 48.02,65.66 47.73,65.36 47.73,64.2 46.8,63.27 40.24,63.27 39.03,62.06 36.41,62.06 35.56,61.21 35.56,55.04 36.5,54.1 v1(37.97,54.1)
AD243X_SDA: length 60.5
  TOP w0.178: U11.15 38.52,54.32 v1(37.97,54.86) 37.97,55.24 36.7,56.52 R78.2 ; S1.3A 71.24,52.59 v1(71.88,51.94) 71.26,51.32 S1.4A
  BOTTOM w0.178: v1(71.88,51.94) 70.68,53.15 68.81,53.15 56.68,65.28 48.29,65.28 48.11,65.1 48.11,64.04 46.96,62.89 40.4,62.89 39.19,61.68 36.66,61.68 35.94,60.96 35.94,55.93 37.01,54.86 v1(37.97,54.86)
AD243X_SIO0: length 31.7
  TOP w0.178: R5.2 47.18,64.2 v1(46.29,64.2) 46.29,60.39 45.2,59.3 U11.5
  BOTTOM w0.178: JP1.2 27.81,63.37 30.99,63.37 32.98,65.37 45.12,65.37 v1(46.29,64.2)
AD243X_SIO1: length 110.5
  TOP w0.178: U11.6 44.7,59.56 45.71,60.57 v1(45.71,62.27) ; v1(60.58,44.96) C40.2 R37.2 ; R6.2 v1(48.89,64.21) ; R38.2 v1(30.1,44.32)
  L3_PWR w0.178: v1(48.89,64.21) 46.96,62.27 v1(45.71,62.27) 44.74,63.25 43.69,63.25 41.78,61.34 36.99,61.34 33.78,58.14 33.78,51.69 32,49.91 29.46,49.91 29.21,49.66 29.21,44.58 29.46,44.32 v1(30.1,44.32)
  BOTTOM w0.178: v1(30.1,44.32) 30.1,43.31 34.12,39.28 35.9,39.28 38.35,36.83 44.2,36.83 45.85,38.48 46.35,38.48 46.67,38.16 46.67,35.78 41.66,30.76 41.66,28.46 42.16,27.95 42.16,26.8 42.55,26.42 45.47,26.42 50.55,31.5 50.55,33.4 57.53,40.39 58.99,40.39 60.58,41.97 v1(60.58,44.96)
AD243X_SIO2: length 81.8
  TOP w0.178: v1(45.17,61.09) 44.2,60.12 U11.7 ; DS3.C 62.95,55.16 62.99,55.2 ; 62.99,55.2 S2.2B ; 62.99,55.2 S2.1B R26.2 56.77,55.96 v1(56.77,58.42)
  BOTTOM w0.178: v1(56.77,58.42) 56.77,64.39 56.39,64.77 50.42,64.77 49.02,63.37 48.13,63.37 45.85,61.09 v1(45.17,61.09) 44.83,61.42 44.83,61.93 44.27,62.48 40.64,62.48 39.46,61.3 36.92,61.3 36.45,60.83 36.45,56.13 37.2,55.38 38.19,55.38 38.49,55.08 38.49,53.66 38.3,53.47 35.31,53.47 34.16,54.61 34.16,56.9 33.53,57.53 31.37,57.53 28.32,54.48 26.19,54.48 P15.7
AD243X_SIO3: length 96.3
  TOP w0.178: R67.1 v1(50.93,108.97) ; R4.2 v1(43.81,64.21)
  L3_PWR w0.178: v1(33.24,56.9) 33.24,58.35 36.61,61.72 41.33,61.72 v1(43.81,64.21) 44.51,64.9 49.53,64.9 50.89,66.26 50.89,71.98 52.22,73.32 52.74,73.32 55.24,75.82 55.24,79.76 54.61,80.39 50.04,80.39 49.15,81.28 49.15,88.64 51.45,90.93 55.37,90.93 56.01,91.57 56.01,105.16 54.61,106.55 54.61,109.93 54.43,110.11 51.18,110.11 50.93,109.86 v1(50.93,108.97)
  BOTTOM w0.178: R12.1 40.14,53.92 38.79,52.58 34.8,52.58 33.24,54.14 v1(33.24,56.9)
AD243X_SIO4: length 32
  TOP w0.178: U12.11 47.24,76.58 v1(47.62,76.2) ; v1(41.27,64.23) 41.3,64.21 R3.2 ; v1(32.13,58.93) R15.1
  L3_PWR w0.178: v1(32.13,58.93) 35.94,62.74 37.72,62.74 39.22,64.23 v1(41.27,64.23) 43.43,66.39 43.43,70.48 44.07,71.12 44.32,71.12 47.62,74.42 v1(47.62,76.2)
AD243X_SYNC: length 65
  TOP w0.178: R2.2 v1(39.57,63.37) 39.57,62.79 39.88,62.48 42.24,62.48 42.42,62.31 R9.1 ; v1(45.74,78.75) U12.8 ; v1(47.5,80.53) U12.16 ; R59.1 v1(53.21,108.97)
  L3_PWR w0.178: v1(39.57,63.37) 41.4,63.37 43.94,65.91 45.21,65.91 45.97,66.67 45.97,70.37 47.58,71.97 47.72,71.97 48.04,72.29 48.04,72.44 49.02,73.42 49.02,76.07 47.5,77.6 46.9,77.6 v1(45.74,78.75) 45.74,78.77 v1(47.5,80.53) 47.84,80.87 47.84,89.5 49.02,90.68 49.02,98.55 53.21,102.74 v1(53.21,108.97)
AD243X_VOUT2: length 87.1
  TOP w0.254: U11.45 v1(49.28,53.82) ; 44.7,48.51 U11.31
  TOP w0.508: R115.1 v1(76.7,23.49) ; C9.1 v1(53.98,53.47) v1(53.47,53.47) 51.18,53.47 50.83,53.82 v1(49.28,53.82)
  L3_PWR w0.508: v1(70.1,66.03) v1(70.1,65.52) 66.69,62.1 63.75,62.1 58.67,57.02 54.86,57.02 53.98,56.13 53.98,53.98 ; 53.98,52.96 v1(53.98,53.47) ; 53.98,52.96 55.12,51.82 66.17,51.82 67.06,52.7 74.22,52.7 74.73,52.2 74.73,32.79 76.7,30.82 v1(76.7,23.49) ; 53.98,52.96 v1(53.47,53.47) ; v1(53.98,53.47) 53.98,53.98 ; v1(53.98,53.47) v1(53.47,53.47) ; 53.98,53.98 v1(53.47,53.47)
  BOTTOM w0.508: v1(43.69,61.84) 43.69,61.84 v1(43.69,61.34) R104.1
  vias: v1(44.3,44.19) v1(44.71,45.33) v1(44.68,44.57) v1(44.68,43.74) v1(45.06,44.19)
ADAU1701_MP6: length 42.4
  TOP w0.178: R70.1 v1(52.58,77.85)
  L3_PWR w0.178: v1(52.58,77.85) 52.2,77.85 50.2,75.86 50.2,72.57 48.51,70.88 48.51,66.8 47.24,65.53 44.37,65.53 40.94,62.1 36.45,62.1 32.64,58.29 31.37,58.29 30.1,59.56 30.1,63.63 JP1.3
ADAU1701_SCL: length 63.9
  TOP w0.178: P10.1 63.25,84.84 53.21,84.84 52.4,84.03 U12.23 ; S1.2B v1(79.25,53.86) ; R74.2 v1(80.4,59.43)
  BOTTOM w0.178: P10.1 65.02,77.85 65.79,77.09 72.01,77.09 80.4,68.7 v1(80.4,59.43) 79.12,58.15 79.12,56.9 80.64,55.37 80.64,54.48 80.02,53.86 v1(79.25,53.86)
ADAU1701_SDA: length 69.7
  TOP w0.178: S1.4B v1(79.25,51.32) ; U12.22 52.67,83.53 53.59,84.45 65.41,84.45 P10.3 ; R75.2 v1(80.4,58.16)
  BOTTOM w0.178: v1(79.25,51.32) 80.02,50.55 81.79,50.55 82.3,51.05 82.3,56.26 v1(80.4,58.16) 81.41,59.17 81.41,70.74 71.69,80.45 68.52,80.45 67.56,81.41 P10.3
AN: length 23.7
  TOP w0.241: U11.28 43.2,48.42 arc(43.23,48.37) 43.25,48.31 43.25,47.84 arc(43.2,47.6) 43.06,47.41 39.1,43.44 arc(38.4,42.98) 37.58,42.81 34.21,42.81 arc(32.82,42.24) 32.24,40.84 32.24,36.72 arc(32.2,36.5) v1(32.07,36.31) 32.07,35.85 C17.2 32.24,35.42 32.24,34.66 32.03,34.45 L2.1
  BOTTOM w0.241: D6.1 31.49,36.07 31.73,36.31 v1(32.07,36.31)
AP: length 23.7
  TOP w0.241: U11.29 43.7,48.42 arc(43.67,48.37) 43.65,48.31 43.65,47.84 arc(43.58,47.46) 43.36,47.13 39.39,43.16 arc(38.56,42.6) 37.58,42.41 34.21,42.41 arc(33.11,41.95) 32.65,40.84 32.65,36.72 arc(32.69,36.5) v1(32.82,36.31) 32.82,35.85 C17.1 32.65,35.42 32.65,34.66 32.86,34.45 L1.1
  BOTTOM w0.241: D6.2 33.4,36.06 33.15,36.31 v1(32.82,36.31)
BN: length 23.7
  TOP w0.241: L4.1 57.37,34.45 57.16,34.66 57.16,35.42 C25.2 57.33,35.85 v1(57.33,36.31) arc(57.2,36.5) 57.16,36.72 57.16,40.84 arc(56.58,42.24) 55.19,42.81 51.82,42.81 arc(51,42.98) 50.3,43.44 46.34,47.41 arc(46.2,47.6) 46.15,47.84 46.15,48.31 arc(46.17,48.37) 46.2,48.42 U11.34
  BOTTOM w0.241: v1(57.33,36.31) 57.66,36.31 57.91,36.06 D4.2
BP: length 23.7
  TOP w0.241: U11.33 45.7,48.42 arc(45.73,48.37) 45.75,48.31 45.75,47.84 arc(45.82,47.46) 46.04,47.13 50.01,43.16 arc(50.84,42.6) 51.82,42.41 55.19,42.41 arc(56.29,41.95) 56.75,40.84 56.75,36.72 arc(56.71,36.5) v1(56.58,36.31) 56.58,35.85 C25.1 56.75,35.42 56.75,34.66 56.54,34.45 L3.1
  BOTTOM w0.241: v1(56.58,36.31) 56.24,36.31 56,36.07 D4.1
ISENSEP: length 30.1
  TOP w0.254: v1(49.77,51.67) 49.77,51.8 49.25,52.32 U11.42
  BOTTOM w0.406: R35.2 65.35,44.51 58.8,51.05 51.04,51.05 50.42,51.67 v1(49.77,51.67)
MP1: length 20.1
  TOP w0.178: v1(46.99,78.99) 46.74,78.75 U12.10
  BOTTOM w0.178: v1(46.99,78.99) 46.48,79.5 46.48,80.91 45.47,81.93 45.47,82.41 46.52,83.47 46.52,87.97 45.34,89.15 44.2,89.15 P5.1
MP2: length 8.5
  TOP w0.254: P5.3 43.69,92.2 43.69,91.06 45.74,89 U12.29
MP3: length 7.7
  TOP w0.254: U12.28 46.24,89.39 45.21,90.42 45.21,93.2 P5.5
MP7: length 18.5
  TOP w0.178: v1(51.69,79.76) 51.43,80.01 50.67,80.01 50.19,79.53 U12.14
  BOTTOM w0.178: P5.7 52.45,88.52 52.45,80.52 v1(51.69,79.76)
MP8: length 8.7
  TOP w0.254: U12.27 46.74,89.65 P5.9
MP9: length 10.5
  TOP w0.254: U12.26 47.24,89.15 49.66,91.57 51.2,91.57 P5.11
MUTE: length 107.7
  TOP w0.178: R103.2 v1(31.75,52.58) ; DS6.C JP3.3
  BOTTOM w0.178: JP3.3 59.82,99.19 59.31,98.68 59.31,91.06 60.32,90.04 60.32,80.52 64.39,76.45 64.39,67.87 62.56,66.04 47.86,66.04 47.35,65.52 47.35,64.35 46.64,63.65 40.36,63.65 39.33,64.68 35.73,64.68 33.91,62.86 23.75,62.86 23.11,62.23 23.11,52.45 23.62,51.94 29.46,51.94 30.1,52.58 v1(31.75,52.58)
PDM_OUT2: length 68.8
  TOP w0.178: v1(46.86,26.42) C41.2 R39.2 ; R40.2 v1(46.1,37.72)
  BOTTOM w0.178: v1(46.86,26.42) 46.23,25.78 42.35,25.78 40.98,27.15 40.98,30.63 46.1,35.75 v1(46.1,37.72) 45.72,37.72 44.32,36.32 36.21,36.32 35.79,36.74 34.25,36.74 22.23,48.77 22.23,63.63 JP1.1
PERIPH_EN: length 31
  TOP w0.254: U10.5 v1(78.23,27.68)
  TOP w0.508: v1(85.09,48.39) R105.2 R106.1
  L3_PWR w0.305: v1(85.09,48.39) 86.11,47.37 86.11,29.97 83.06,26.92 81.41,26.92 80.64,27.69 78.23,27.69 v1(78.23,27.68)
SPI_CS/ADR1: length 17.7
  TOP w0.178: P15.9 26.16,51.92 32.96,51.92 33.52,52.48 R103.1 34.22,51.88 38.04,51.88 39.1,50.82 U11.22
SWP: length 34.8
  TOP w0.254: U11.41 48.89,51.82 49,51.71 v1(49.06,51.71)
  BOTTOM w0.406: v1(49.06,51.71) 49.06,51.49 49.62,50.93 50.3,50.93 50.78,50.44 58.47,50.44 61.85,47.06 R33.1
UNNAMED_2_AD243XW_I16_ACM: length 2.8
  TOP w0.254: U11.27 v1(42.7,48.64)
  BOTTOM w0.508: C15.1 43.18,49.12 v1(42.7,48.64) 43.08,48.26 C14.1
UNNAMED_2_AD243XW_I16_ADR2: length 7.9
  TOP w0.178: U11.23 38.64,50.32 37.71,51.24 R11.2
UNNAMED_2_AD243XW_I16_BCLK: length 5.6
  TOP w0.178: U11.9 43.2,56.9 43.44,57.14 43.44,58.42 R10.2
UNNAMED_2_AD243XW_I16_BCM: length 2.8
  TOP w0.254: U11.35 v1(46.7,48.64)
  BOTTOM w0.508: C10.2 46.3,48.26 46.68,48.64 v1(46.7,48.64) 46.7,48.68 C12.2
UNNAMED_2_AD243XW_I16_DVDD1: length 8.7
  TOP w0.254: U11.48 48.41,55.32 v1(48.67,55.06) 48.43,54.82 U11.47 ; U11.2 46.7,56.61 46.45,56.87 v1(46.2,56.87) U11.3
  TOP w0.508: v1(46.2,56.87) v1(46.2,57.4)
  L2_GND w0.508: v1(46.2,57.4) v1(46.2,56.87)
  L3_PWR w0.508: v1(46.2,57.4) v1(46.2,56.87)
  BOTTOM w0.508: C4.1 48.06,54.61 48.51,55.06 v1(48.67,55.06) ; v1(46.2,57.4) v1(46.2,56.87) 45.96,56.62 C2.1 45.46,56.63 C1.1
UNNAMED_2_AD243XW_I16_ISENSEN: length 12.4
  TOP w0.254: U11.36 48.16,49.12 48.63,49.59 52.39,49.59 52.96,50.16 52.96,50.47 R18.1 52.07,50.67 51.51,50.12 48.64,50.12 48.38,49.86 47.94,49.86 U11.37
UNNAMED_2_AD243XW_I16_MISO: length 8.9
  TOP w0.178: R100.1 34.13,55.4 34.13,54.9 35.71,53.32 U11.17
UNNAMED_2_AD243XW_I16_MOSI: length 8.3
  TOP w0.178: U11.18 35.57,52.82 R101.1
UNNAMED_2_AD243XW_I16_RSTB: length 40.5
  TOP w0.178: R87.1 v1(19.05,46.6) ; U11.25 v1(41.05,49.12)
  L3_PWR w0.178: v1(19.05,46.6) 19.05,43.69 20.83,41.91 37.46,41.91 41.53,45.97 41.53,48.64 v1(41.05,49.12)
  BOTTOM w0.178: R97.2 35.93,51.64 36.11,51.82 38.08,51.82 38.22,51.68 C81.1 38.95,51.18 39.33,50.8 40.77,50.8 41.05,50.52 v1(41.05,49.12)
UNNAMED_2_AD243XW_I16_SCK: length 8.1
  TOP w0.178: R102.1 34.91,52.32 U11.19
UNNAMED_2_AD243XW_I16_SIO3: length 2.7
  TOP w0.178: U11.12 v1(41.09,56.02)
  BOTTOM w0.178: v1(41.09,56.02) 41.09,54.02 R12.2
UNNAMED_2_AD243XW_I16_SIO4: length 6.9
  TOP w0.178: U11.13 39.3,55.32 37.72,56.9 37.72,58.62 37.41,58.93 R15.2
